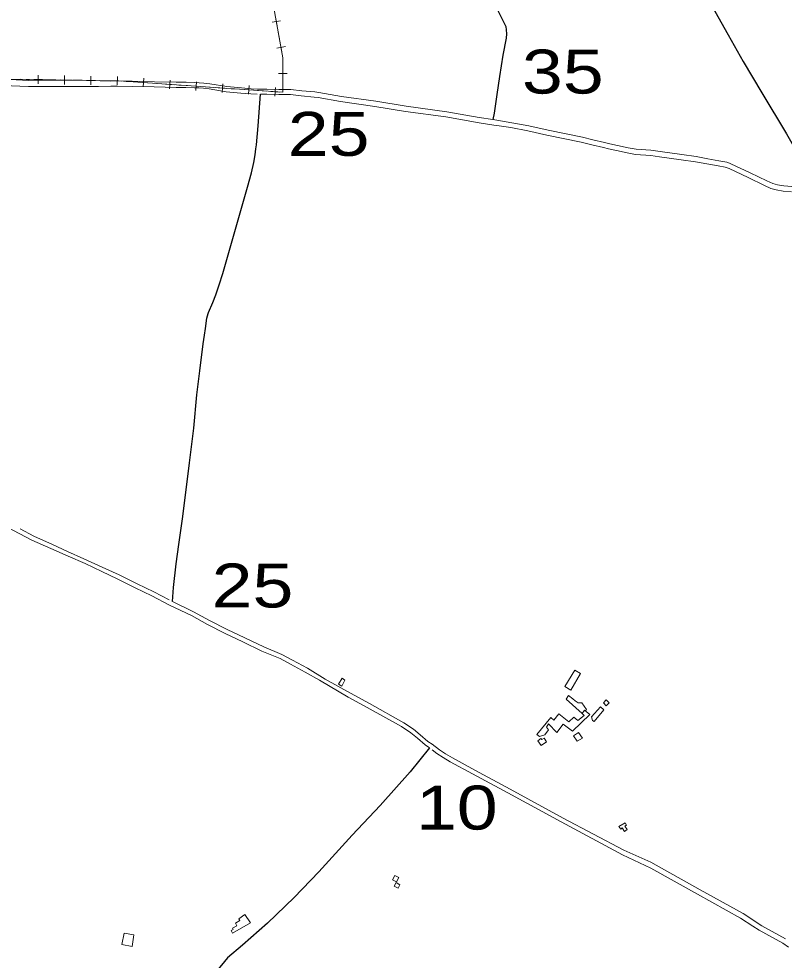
# Model space of a CAD drawing. Extents: x 476989 to 498418, y 4381813 to 4416555.
# Drawn here: x 484730 to 485600, y 4386760 to 4387830 of the extents above; entities that cross this region are included whole.
import ezdxf
from ezdxf.enums import TextEntityAlignment as Align

# ---------------------------------------------------------------- set-up
doc = ezdxf.new("R2010")
doc.units = 0
doc.header["$LTSCALE"] = 20
for name, color, linetype, lineweight in [('13', 7, 'Continuous', 13), ('34', 7, 'Continuous', 13), ('36', 7, 'Continuous', 13), ('47', 7, 'Continuous', 13), ('6', 7, 'Continuous', 25)]:
    doc.layers.add(name, color=color, linetype=linetype, lineweight=lineweight)

msp = doc.modelspace()

# ---------------------------------------------------------------- linework, layer by layer
at = {"layer": '34'}
for p, q in [((485021.6, 4387832.42), (485023.38, 4387822.58)), ((485017.57, 4387826.61), (485027.41, 4387828.39)), ((485024.27, 4387817.66), (485026.05, 4387807.82)), ((485022.91, 4387797.09), (485032.75, 4387798.87)), ((485026.94, 4387802.9), (485028.72, 4387793.06)), ((484751.71, 4387766.39), (484751.56, 4387756.4)), ((485025, 4387768.17), (485035, 4387768.17)), ((485030, 4387773.17), (485030, 4387763.17)), ((484741.63, 4387761.55), (484731.64, 4387761.7)), ((484756.63, 4387761.32), (484746.63, 4387761.47)), ((484771.63, 4387761.09), (484761.63, 4387761.24)), ((484786.63, 4387760.86), (484776.63, 4387761.01)), ((484781.71, 4387765.94), (484781.55, 4387755.94)), ((484801.63, 4387760.63), (484791.63, 4387760.78)), ((484816.63, 4387760.4), (484806.63, 4387760.56)), ((484811.7, 4387765.48), (484811.55, 4387755.48)), ((484831.62, 4387760.17), (484821.62, 4387760.33)), ((484841.7, 4387765.02), (484841.55, 4387755.02)), ((484861.58, 4387758.71), (484851.6, 4387759.4)), ((484876.54, 4387757.67), (484866.57, 4387758.36)), ((484871.9, 4387763), (484871.21, 4387753.03)), ((484891.5, 4387756.63), (484881.53, 4387757.32)), ((484906.47, 4387755.59), (484896.49, 4387756.28)), ((484901.83, 4387760.92), (484901.13, 4387750.95)), ((484931.76, 4387758.84), (484931.06, 4387748.87)), ((484961.68, 4387756.76), (484960.99, 4387746.79)), ((485030, 4387758.17), (485030, 4387748.17)), ((484921.43, 4387754.55), (484911.46, 4387755.24)), ((484936.4, 4387753.51), (484926.42, 4387754.2)), ((484951.36, 4387752.47), (484941.38, 4387753.16)), ((484966.32, 4387751.43), (484956.35, 4387752.12)), ((484981.29, 4387750.39), (484971.31, 4387751.08)), ((484996.25, 4387749.35), (484986.28, 4387750.04)), ((484991.61, 4387754.68), (484990.92, 4387744.7)), ((485011.22, 4387748.31), (485001.24, 4387749)), ((485026.18, 4387747.27), (485016.2, 4387747.96)), ((485021.54, 4387752.6), (485020.85, 4387742.62))]:
    msp.add_line(p, q, dxfattribs=at)
for points in [[(484742, 4388368), (484968, 4388081), (484988, 4388018), (485030, 4387786), (485030, 4387747), (484843, 4387760), (484712, 4387762), (484623, 4387793), (484342, 4387807), (484273, 4387819), (484108.44, 4387807.03)], [(485029.61, 4387788.14), (485030, 4387786), (485030, 4387778.17)], [(484846.61, 4387759.75), (484843, 4387760), (484836.62, 4387760.1)]]:
    msp.add_lwpolyline(points, dxfattribs=at)
at = {"layer": '36'}
for points in [[(484798.95, 4387753.61), (484740.73, 4387753.43), (484711.52, 4387754.84), (484691.22, 4387758.64), (484678.76, 4387763.13), (484663.74, 4387768.84), (484653.58, 4387774.86), (484642.8, 4387780.89), (484632.55, 4387784.9), (484626.77, 4387786.76), (484614.38, 4387788.44), (484579.29, 4387793.34), (484491.86, 4387799.73)], [(484798.93, 4387760.7), (484740.89, 4387760.52), (484712.35, 4387761.9), (484693.08, 4387765.5), (484681.23, 4387769.77), (484666.83, 4387775.25), (484657.12, 4387781), (484645.83, 4387787.32), (484634.93, 4387791.59), (484628.34, 4387793.7), (484615.13, 4387795.49), (484580.58, 4387800.8), (484492.14, 4387806.72)], [(484798.93, 4387760.7), (484834.03, 4387759.68), (484840.94, 4387759.89), (484858.69, 4387759.43), (484883.86, 4387758.86), (484908.49, 4387758.47), (484919.79, 4387758.31), (484929.83, 4387758.04), (484934.93, 4387757.78), (484940.17, 4387757.35), (484946.81, 4387756.64), (484966.32, 4387753.46), (484982.82, 4387751.87), (484993.84, 4387750.94), (485001.08, 4387750.58), (485011.81, 4387750.66), (485025.45, 4387750.29), (485038.89, 4387750.19), (485051.42, 4387748.65), (485066.32, 4387747.42), (485070.86, 4387746.77), (485096.5, 4387742.28), (485135.5, 4387736.71), (485170.14, 4387731.03), (485216.24, 4387724.72), (485253.12, 4387718.26), (485268.79, 4387715.93), (485270.96, 4387715.52), (485290.18, 4387712.13), (485309.62, 4387708.84), (485331.43, 4387704.04), (485370.49, 4387695.9), (485382.54, 4387692.96), (485395.76, 4387690.01), (485401.7, 4387688.38), (485410.35, 4387686.48), (485422.59, 4387683.93), (485431.58, 4387682.19), (485448.2, 4387681.05)], [(484798.95, 4387753.61), (484820.12, 4387753.58), (484834.17, 4387753.81), (484840.95, 4387754.01), (484858.55, 4387753.56), (484883.74, 4387752.99), (484908.41, 4387752.6), (484919.67, 4387752.44), (484929.6, 4387752.17), (484934.54, 4387751.92), (484939.61, 4387751.5), (484946.03, 4387750.81), (484965.57, 4387747.63), (484982.29, 4387746.02), (484993.45, 4387745.08), (485000.69, 4387744.72)], [(485004.65, 4387744.73), (485011.76, 4387744.78), (485025.35, 4387744.41), (485038.51, 4387744.32), (485050.82, 4387742.8), (485065.65, 4387741.58), (485069.93, 4387740.96), (485095.58, 4387736.47), (485134.61, 4387730.9), (485169.26, 4387725.22), (485215.38, 4387718.9), (485253.12, 4387712.35), (485269.91, 4387709.7), (485276.03, 4387708.96), (485289.33, 4387706.75), (485308.29, 4387703.12), (485330.2, 4387698.29), (485369.19, 4387690.16), (485381.21, 4387687.24), (485394.34, 4387684.31), (485400.29, 4387682.67), (485409.12, 4387680.73), (485421.43, 4387678.16), (485430.75, 4387676.36), (485448.2, 4387675.12)], [(485448.2, 4387681.05), (485458.98, 4387679.52), (485483.62, 4387676.09), (485499.96, 4387673.83), (485513.05, 4387671.47), (485525.85, 4387669.03), (485534.71, 4387667.62), (485537.94, 4387666.38), (485539.28, 4387665.58), (485561.41, 4387655.37), (485580.28, 4387646.32), (485586.96, 4387643.16), (485592.33, 4387641.73), (485599.42, 4387640.44), (485608.78, 4387639.71)], [(485448.2, 4387675.12), (485458.17, 4387673.7), (485482.82, 4387670.27), (485499.03, 4387668.02), (485511.98, 4387665.69), (485524.84, 4387663.24), (485532.77, 4387661.98), (485537.4, 4387660.22), (485559.04, 4387649.99), (485577.75, 4387641.02), (485584.93, 4387637.62), (485591.05, 4387636), (485598.66, 4387634.6), (485608.4, 4387633.84)], [(484716.6, 4387252.46), (484744.57, 4387237.87), (484765.96, 4387228.04), (484785.95, 4387219.5), (484804.94, 4387211.05), (484823.92, 4387201.9), (484841.33, 4387193.76), (484861.92, 4387183.47), (484880.95, 4387174.47), (484900.92, 4387163.88), (484925.9, 4387151.85), (484944.1, 4387141.99), (484964.47, 4387131.61), (484984.32, 4387121.95), (485006.12, 4387111.66), (485026.67, 4387103.08), (485038.55, 4387096.84), (485055.45, 4387087.66), (485071.49, 4387078.37), (485104.22, 4387059.29), (485125.9, 4387047.57), (485164.72, 4387025.8), (485175.49, 4387018.62), (485182.86, 4387012.44), (485191.84, 4387004.83), (485196.68, 4387001.41)], [(484731.26, 4387250.54), (484746.8, 4387242.43), (484768.02, 4387232.68), (484785.12, 4387224.95), (484803.58, 4387216.58), (484824.62, 4387206.9), (484843.61, 4387198.29), (484864.14, 4387188.04), (484883.22, 4387179.01), (484900.49, 4387169.86)], [(484904.27, 4387167.9), (484928.21, 4387156.37), (484946.46, 4387146.48), (484966.73, 4387136.15), (484986.51, 4387126.53), (485008.19, 4387116.3), (485028.83, 4387107.68), (485040.94, 4387101.32), (485057.93, 4387092.09), (485077.85, 4387079.8), (485106.7, 4387063.72), (485128.35, 4387052.02), (485167.37, 4387030.13), (485178.54, 4387022.69), (485186.13, 4387016.32), (485194.95, 4387008.84), (485199.56, 4387005.59), (485207.95, 4386999.32), (485214.97, 4386994.81), (485222.72, 4386990.21), (485248.09, 4386976.31), (485288.29, 4386954.73), (485348.62, 4386921.76), (485417.64, 4386885.14), (485448.2, 4386871.57)], [(485199.66, 4386999.18), (485205.06, 4386995.15), (485212.3, 4386990.49), (485220.21, 4386985.8), (485245.67, 4386971.85), (485285.88, 4386950.27), (485346.2, 4386917.3), (485416.17, 4386880.07), (485448.2, 4386864.89)], [(485448.2, 4386871.57), (485504.34, 4386840.28), (485553.22, 4386813.06), (485574.47, 4386799.34), (485601.49, 4386784.39)], [(485448.2, 4386864.89), (485501.51, 4386835.18), (485550.21, 4386808.06), (485564.49, 4386798.84)], [(485564.49, 4386798.84), (485571.47, 4386794.33), (485598.37, 4386779.45), (485604.95, 4386774.75)]]:
    msp.add_lwpolyline(points, dxfattribs=at)
at = {"layer": '47'}
for points in [[(485368.22, 4387086.2), (485357.27, 4387067.19), (485350.67, 4387071.13), (485362.11, 4387089.78)], [(485097.24, 4387080.64), (485100.57, 4387078.42), (485096.97, 4387071.84), (485093.08, 4387073.8)], [(485394.39, 4387052.63), (485397.68, 4387049.39), (485401.01, 4387052.87), (485397.7, 4387056.05)], [(485372.99, 4387044.3), (485379, 4387039.44), (485359.12, 4387020.48), (485348.48, 4387028.62), (485341.4, 4387019.09), (485332.09, 4387028.81), (485329.57, 4387025.05), (485331.9, 4387022.2), (485327.68, 4387016.19), (485321.58, 4387014.58), (485318.65, 4387016.84), (485334.49, 4387035.93), (485338.08, 4387032.94), (485343.81, 4387040.06), (485355.18, 4387030.96), (485360.7, 4387036.3), (485365.34, 4387032.5), (485372.61, 4387038.49), (485370.16, 4387040.56)], [(485391.11, 4387048.23), (485395.02, 4387044.71), (485384.02, 4387031.63), (485382.12, 4387032.82), (485380.94, 4387036.71)], [(485366.04, 4387018.89), (485370.57, 4387012.53), (485364.64, 4387009.06), (485360.3, 4387015.36)], [(485327, 4387012.45), (485329.8, 4387008.42), (485323.53, 4387004.21), (485319.77, 4387009.59), (485323.16, 4387012.07), (485324.25, 4387010.89)], [(485414.1, 4386909.21), (485412, 4386912.03), (485419.3, 4386916.24), (485420.78, 4386913.81), (485418.73, 4386912.47), (485421.25, 4386908.69), (485418.22, 4386906.38), (485415.81, 4386910.6)], [(485159.11, 4386849.19), (485161.77, 4386854.02), (485157.33, 4386856.45), (485154.56, 4386851.45)], [(485158.77, 4386848.3), (485163.02, 4386845.74), (485161.19, 4386841.81), (485156.57, 4386844.26)], [(484986.77, 4386812.07), (484993.03, 4386802.65), (484972.62, 4386790.82), (484971.23, 4386794), (484973.4, 4386795.11), (484972.72, 4386796.45), (484977.43, 4386799.32), (484975.89, 4386802.33), (484981.16, 4386805.24), (484980.03, 4386807.2)], [(484849.44, 4386790.77), (484846.94, 4386777.85), (484858.51, 4386775.82), (484860.5, 4386788.91)]]:
    msp.add_lwpolyline(points, close=True, dxfattribs=at)
msp.add_lwpolyline([(485370.16, 4387040.56), (485352.1, 4387056.87), (485354.61, 4387061.18), (485359.78, 4387057.35), (485362.15, 4387054.85), (485365.59, 4387052.79), (485369.74, 4387052.73), (485375.25, 4387045.3), (485374.01, 4387043.48)], dxfattribs=at)
at = {"layer": '6'}
for points in [[(485361.68, 4388171.46), (485378.46, 4388133.46), (485401.8, 4388082.2), (485421.34, 4388037.69), (485434.11, 4388003.69), (485451.8, 4387971.36), (485466.24, 4387934.48), (485477.35, 4387911.58), (485495.47, 4387882.54), (485517.79, 4387845.13), (485536.33, 4387812.23), (485553.28, 4387782.16)], [(485126.61, 4388148.09), (485133.89, 4388132.19), (485146.45, 4388109.63), (485159.7, 4388079.42), (485173.4, 4388051.16), (485187.78, 4388020.66), (485202.68, 4387988.5), (485223.68, 4387944.5), (485241.45, 4387906.87), (485258.16, 4387874.34), (485274.72, 4387839.19), (485283.44, 4387821.96), (485283.82, 4387817.85), (485284.05, 4387813.43), (485283.91, 4387808.34), (485279.89, 4387789.2)], [(485279.89, 4387789.2), (485276.31, 4387764.85), (485273.22, 4387744.39), (485270.15, 4387723.13), (485268.79, 4387715.93)], [(485553.28, 4387782.16), (485574.6, 4387746.28), (485602.45, 4387699.59), (485635.65, 4387642.16), (485636.43, 4387640.27), (485636.65, 4387638.03)], [(484904.27, 4387167.9), (484905.66, 4387183.86), (484908.57, 4387210.82), (484911.66, 4387232.66), (484916.02, 4387264.71), (484923.85, 4387325.72), (484928.6, 4387365.22), (484931.97, 4387402.9), (484935.53, 4387430.32), (484939.12, 4387461.07), (484940.92, 4387470.98), (484942.02, 4387478.39), (484943.44, 4387490.05), (484944.88, 4387495.32), (484945.51, 4387496.66), (484950.42, 4387507.8), (484953.76, 4387516.7), (484957.52, 4387528.13), (484961.56, 4387540.98), (484966.88, 4387559.67), (484976.87, 4387594.07), (484982.74, 4387615.17), (484989.84, 4387639.07), (484994.09, 4387655.51), (484996.91, 4387666.98), (484998.31, 4387675.88), (484999.26, 4387682.75), (484999.77, 4387687.23), (485001.75, 4387708.92), (485004.65, 4387744.73)], [(485196.68, 4387001.41), (485174.53, 4386974.43), (485140.42, 4386936.16), (485108.67, 4386902.09), (485070.95, 4386860.47), (485042.96, 4386831.45), (485012.41, 4386802.17), (484984.19, 4386777.31), (484966.85, 4386762.96), (484954.68, 4386748.08), (484950.17, 4386739.57), (484953.68, 4386722.28), (484969.49, 4386709.51)]]:
    msp.add_lwpolyline(points, dxfattribs=at)

# ---------------------------------------------------------------- texts
at = {"layer": '13', "width": 1.25}
for s, p in [('35', (485348.25, 4387745.52)), ('25', (485081.99, 4387674.67)), ('25', (484995.38, 4387161.14)), ('10', (485227.72, 4386908.63))]:
    msp.add_text(s, height=50, dxfattribs=at).set_placement(p, align=Align.CENTER)

doc.saveas('drawing.dxf')
